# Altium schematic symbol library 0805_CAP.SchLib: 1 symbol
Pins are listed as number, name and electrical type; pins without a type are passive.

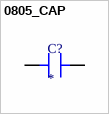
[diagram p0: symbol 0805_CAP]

## 0805_CAP
designator C?
0805 cap; MF: AVX; MP: 08055C102K4T2A
footprint 0805
pins: 1, 2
